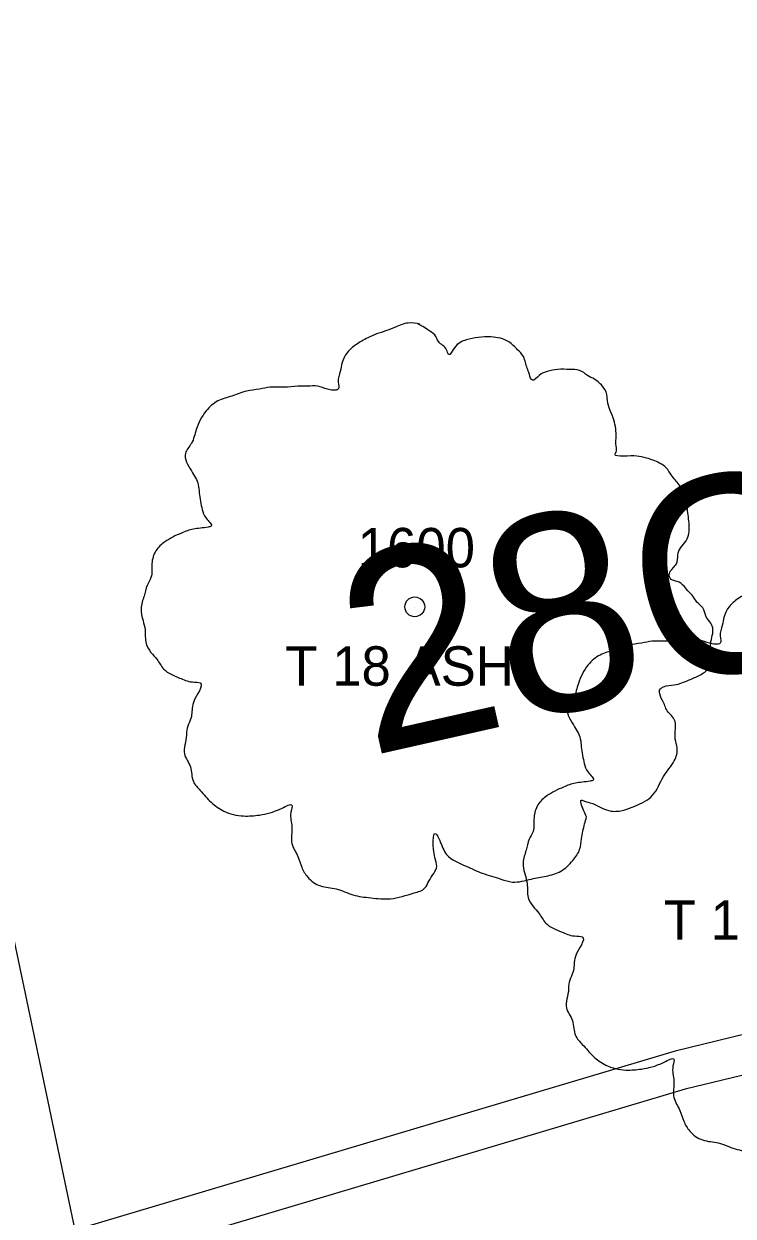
# Model space of a CAD drawing. Extents: x 1964982 to 1970452, y 1116335 to 1119906.
# Drawn here: x 1966603.01 to 1966621, y 1117434.1 to 1117464.33 of the extents above; entities that cross this region are included whole.
import ezdxf

# ---------------------------------------------------------------- set-up
doc = ezdxf.new("R2010")
doc.units = 0
for name, color, linetype in [('RD_EX_VEG', 7, 'Continuous'), ('RD_EX_VEG_txCode', 7, 'Continuous'), ('RD_HC_CL_Rel', 7, 'Continuous'), ('RD_HC_Data_Rel', 7, 'Continuous'), ('RD_PD_CstnLmt', 7, 'Continuous'), ('RD_PD_Final_TrvlWay', 7, 'Continuous'), ('RD_PD_RW', 7, 'Continuous'), ('RD_PD_TX_CstnLmt', 7, 'Continuous')]:
    doc.layers.add(name, color=color, linetype=linetype)

msp = doc.modelspace()

# ---------------------------------------------------------------- linework, layer by layer
at = {"layer": 'RD_EX_VEG'}
for centre, radius in [((1966612.923, 1117449.547), 0.25), ((1966612.923, 1117449.547), 0.25), ((1966612.91, 1117449.528), 0.0001), ((1966612.91, 1117449.528), 0.0001)]:
    msp.add_circle(centre, radius, dxfattribs=at)
for points in [[(1966613.054, 1117456.715), (1966612.755, 1117456.74), (1966612.43, 1117456.64), (1966612.18, 1117456.54), (1966611.955, 1117456.465), (1966611.73, 1117456.365), (1966611.43, 1117456.19), (1966611.205, 1117455.99), (1966611.08, 1117455.74), (1966611.03, 1117455.515), (1966610.98, 1117455.24), (1966610.98, 1117455.065), (1966610.855, 1117455.04), (1966610.705, 1117455.065), (1966610.456, 1117455.14), (1966610.206, 1117455.14), (1966609.956, 1117455.14), (1966609.606, 1117455.115), (1966609.256, 1117455.115), (1966608.981, 1117455.065), (1966608.656, 1117455.015), (1966608.282, 1117454.89), (1966607.932, 1117454.765), (1966607.632, 1117454.515), (1966607.382, 1117454.041), (1966607.257, 1117453.691), (1966607.107, 1117453.441), (1966607.257, 1117452.991), (1966607.432, 1117452.641), (1966607.457, 1117452.441), (1966607.532, 1117452.017), (1966607.632, 1117451.792), (1966607.757, 1117451.592), (1966607.682, 1117451.567), (1966607.307, 1117451.517), (1966607.007, 1117451.417), (1966606.582, 1117451.192), (1966606.357, 1117450.967), (1966606.257, 1117450.642), (1966606.232, 1117450.292), (1966606.133, 1117450.092), (1966606.058, 1117449.818), (1966606.033, 1117449.743), (1966605.983, 1117449.418), (1966606.083, 1117448.968), (1966606.108, 1117448.618), (1966606.232, 1117448.393), (1966606.382, 1117448.218), (1966606.557, 1117447.968), (1966606.957, 1117447.743), (1966607.282, 1117447.643), (1966607.482, 1117447.619), (1966607.307, 1117447.119), (1966607.257, 1117446.769), (1966607.132, 1117446.369), (1966607.132, 1117446.294), (1966607.082, 1117445.819), (1966607.232, 1117445.494), (1966607.307, 1117445.12), (1966607.482, 1117444.895), (1966607.757, 1117444.595), (1966608.082, 1117444.37), (1966608.581, 1117444.245), (1966608.981, 1117444.27), (1966609.556, 1117444.445), (1966609.806, 1117444.52), (1966609.781, 1117444.345), (1966609.806, 1117443.97), (1966609.806, 1117443.545), (1966609.956, 1117443.22), (1966610.056, 1117442.946), (1966610.206, 1117442.696), (1966610.531, 1117442.471), (1966610.93, 1117442.396), (1966611.355, 1117442.246), (1966611.805, 1117442.171), (1966612.305, 1117442.146), (1966612.905, 1117442.296), (1966613.179, 1117442.421), (1966613.279, 1117442.596), (1966613.479, 1117442.971), (1966613.429, 1117443.195), (1966613.454, 1117443.795), (1966613.554, 1117443.62), (1966613.729, 1117443.27), (1966614.229, 1117442.971), (1966614.629, 1117442.796), (1966615.104, 1117442.646), (1966615.403, 1117442.571), (1966615.878, 1117442.646), (1966616.253, 1117442.721), (1966616.628, 1117442.846), (1966616.928, 1117443.12), (1966617.103, 1117443.395), (1966617.153, 1117443.67), (1966617.228, 1117444.045), (1966617.278, 1117444.22)], [(1966613.054, 1117456.715), (1966612.755, 1117456.74), (1966612.43, 1117456.64), (1966612.18, 1117456.54), (1966611.955, 1117456.465), (1966611.73, 1117456.365), (1966611.43, 1117456.19), (1966611.205, 1117455.99), (1966611.08, 1117455.74), (1966611.03, 1117455.515), (1966610.98, 1117455.24), (1966610.98, 1117455.065), (1966610.855, 1117455.04), (1966610.705, 1117455.065), (1966610.456, 1117455.14), (1966610.206, 1117455.14), (1966609.956, 1117455.14), (1966609.606, 1117455.115), (1966609.256, 1117455.115), (1966608.981, 1117455.065), (1966608.656, 1117455.015), (1966608.282, 1117454.89), (1966607.932, 1117454.765), (1966607.632, 1117454.515), (1966607.382, 1117454.041), (1966607.257, 1117453.691), (1966607.107, 1117453.441), (1966607.257, 1117452.991), (1966607.432, 1117452.641), (1966607.457, 1117452.441), (1966607.532, 1117452.017), (1966607.632, 1117451.792), (1966607.757, 1117451.592), (1966607.682, 1117451.567), (1966607.307, 1117451.517), (1966607.007, 1117451.417), (1966606.582, 1117451.192), (1966606.357, 1117450.967), (1966606.257, 1117450.642), (1966606.232, 1117450.292), (1966606.133, 1117450.092), (1966606.058, 1117449.818), (1966606.033, 1117449.743), (1966605.983, 1117449.418), (1966606.083, 1117448.968), (1966606.108, 1117448.618), (1966606.232, 1117448.393), (1966606.382, 1117448.218), (1966606.557, 1117447.968), (1966606.957, 1117447.743), (1966607.282, 1117447.643), (1966607.482, 1117447.619), (1966607.307, 1117447.119), (1966607.257, 1117446.769), (1966607.132, 1117446.369), (1966607.132, 1117446.294), (1966607.082, 1117445.819), (1966607.232, 1117445.494), (1966607.307, 1117445.12), (1966607.482, 1117444.895), (1966607.757, 1117444.595), (1966608.082, 1117444.37), (1966608.581, 1117444.245), (1966608.981, 1117444.27), (1966609.556, 1117444.445), (1966609.806, 1117444.52), (1966609.781, 1117444.345), (1966609.806, 1117443.97), (1966609.806, 1117443.545), (1966609.956, 1117443.22), (1966610.056, 1117442.946), (1966610.206, 1117442.696), (1966610.531, 1117442.471), (1966610.93, 1117442.396), (1966611.355, 1117442.246), (1966611.805, 1117442.171), (1966612.305, 1117442.146), (1966612.905, 1117442.296), (1966613.179, 1117442.421), (1966613.279, 1117442.596), (1966613.479, 1117442.971), (1966613.429, 1117443.195), (1966613.454, 1117443.795), (1966613.554, 1117443.62), (1966613.729, 1117443.27), (1966614.229, 1117442.971), (1966614.629, 1117442.796), (1966615.104, 1117442.646), (1966615.403, 1117442.571), (1966615.878, 1117442.646), (1966616.253, 1117442.721), (1966616.628, 1117442.846), (1966616.928, 1117443.12), (1966617.103, 1117443.395), (1966617.153, 1117443.67), (1966617.228, 1117444.045), (1966617.278, 1117444.22)], [(1966617.278, 1117444.22), (1966617.203, 1117444.395), (1966617.153, 1117444.645), (1966617.228, 1117444.62), (1966617.403, 1117444.57), (1966617.677, 1117444.445), (1966617.902, 1117444.37), (1966618.227, 1117444.395), (1966618.502, 1117444.495), (1966618.952, 1117444.77), (1966619.227, 1117445.245), (1966619.502, 1117445.644), (1966619.577, 1117445.969), (1966619.527, 1117446.194), (1966619.502, 1117446.694), (1966619.302, 1117446.944), (1966619.252, 1117447.069), (1966619.152, 1117447.469), (1966619.227, 1117447.519), (1966619.502, 1117447.569), (1966619.876, 1117447.693), (1966620.151, 1117447.818), (1966620.376, 1117447.993), (1966620.451, 1117448.218), (1966620.426, 1117448.618), (1966620.476, 1117449.018), (1966620.401, 1117449.168), (1966620.301, 1117449.318), (1966620.226, 1117449.518), (1966620.076, 1117449.668), (1966619.976, 1117449.818), (1966619.876, 1117449.917), (1966619.752, 1117450.067), (1966619.577, 1117450.192), (1966619.427, 1117450.242), (1966619.377, 1117450.392), (1966619.527, 1117450.592), (1966619.577, 1117450.692), (1966619.602, 1117450.917), (1966619.827, 1117451.267), (1966619.876, 1117451.667), (1966619.827, 1117452.092), (1966619.777, 1117452.366), (1966619.627, 1117452.641), (1966619.427, 1117452.891), (1966619.302, 1117453.066), (1966619.127, 1117453.191), (1966618.802, 1117453.316), (1966618.552, 1117453.366), (1966618.202, 1117453.366), (1966618.002, 1117453.416), (1966618.027, 1117453.466), (1966618.027, 1117453.616), (1966618.027, 1117453.891), (1966617.952, 1117454.341), (1966617.802, 1117454.84), (1966617.802, 1117454.865), (1966617.702, 1117455.115), (1966617.478, 1117455.315), (1966617.303, 1117455.415), (1966617.103, 1117455.54), (1966616.853, 1117455.565), (1966616.553, 1117455.565), (1966616.278, 1117455.515), (1966616.078, 1117455.415), (1966615.903, 1117455.29), (1966615.828, 1117455.44), (1966615.728, 1117455.74), (1966615.678, 1117455.89), (1966615.528, 1117456.065), (1966615.304, 1117456.265), (1966614.854, 1117456.39), (1966614.229, 1117456.315), (1966613.929, 1117456.115), (1966613.779, 1117455.94), (1966613.729, 1117456.065), (1966613.529, 1117456.265), (1966613.429, 1117456.44), (1966613.254, 1117456.565), (1966613.104, 1117456.665), (1966613.004, 1117456.715)], [(1966617.278, 1117444.22), (1966617.203, 1117444.395), (1966617.153, 1117444.645), (1966617.228, 1117444.62), (1966617.403, 1117444.57), (1966617.677, 1117444.445), (1966617.902, 1117444.37), (1966618.227, 1117444.395), (1966618.502, 1117444.495), (1966618.952, 1117444.77), (1966619.227, 1117445.245), (1966619.502, 1117445.644), (1966619.577, 1117445.969), (1966619.527, 1117446.194), (1966619.502, 1117446.694), (1966619.302, 1117446.944), (1966619.252, 1117447.069), (1966619.152, 1117447.469), (1966619.227, 1117447.519), (1966619.502, 1117447.569), (1966619.876, 1117447.693), (1966620.151, 1117447.818), (1966620.376, 1117447.993), (1966620.451, 1117448.218), (1966620.426, 1117448.618), (1966620.476, 1117449.018), (1966620.401, 1117449.168), (1966620.301, 1117449.318), (1966620.226, 1117449.518), (1966620.076, 1117449.668), (1966619.976, 1117449.818), (1966619.876, 1117449.917), (1966619.752, 1117450.067), (1966619.577, 1117450.192), (1966619.427, 1117450.242), (1966619.377, 1117450.392), (1966619.527, 1117450.592), (1966619.577, 1117450.692), (1966619.602, 1117450.917), (1966619.827, 1117451.267), (1966619.876, 1117451.667), (1966619.827, 1117452.092), (1966619.777, 1117452.366), (1966619.627, 1117452.641), (1966619.427, 1117452.891), (1966619.302, 1117453.066), (1966619.127, 1117453.191), (1966618.802, 1117453.316), (1966618.552, 1117453.366), (1966618.202, 1117453.366), (1966618.002, 1117453.416), (1966618.027, 1117453.466), (1966618.027, 1117453.616), (1966618.027, 1117453.891), (1966617.952, 1117454.341), (1966617.802, 1117454.84), (1966617.802, 1117454.865), (1966617.702, 1117455.115), (1966617.478, 1117455.315), (1966617.303, 1117455.415), (1966617.103, 1117455.54), (1966616.853, 1117455.565), (1966616.553, 1117455.565), (1966616.278, 1117455.515), (1966616.078, 1117455.415), (1966615.903, 1117455.29), (1966615.828, 1117455.44), (1966615.728, 1117455.74), (1966615.678, 1117455.89), (1966615.528, 1117456.065), (1966615.304, 1117456.265), (1966614.854, 1117456.39), (1966614.229, 1117456.315), (1966613.929, 1117456.115), (1966613.779, 1117455.94), (1966613.729, 1117456.065), (1966613.529, 1117456.265), (1966613.429, 1117456.44), (1966613.254, 1117456.565), (1966613.104, 1117456.665), (1966613.004, 1117456.715)], [(1966622.743, 1117450.276), (1966622.443, 1117450.301), (1966622.118, 1117450.201), (1966621.868, 1117450.101), (1966621.643, 1117450.026), (1966621.418, 1117449.926), (1966621.118, 1117449.751), (1966620.893, 1117449.551), (1966620.768, 1117449.301), (1966620.718, 1117449.076), (1966620.669, 1117448.801), (1966620.669, 1117448.626), (1966620.544, 1117448.601), (1966620.394, 1117448.626), (1966620.144, 1117448.701), (1966619.894, 1117448.701), (1966619.644, 1117448.701), (1966619.294, 1117448.676), (1966618.944, 1117448.676), (1966618.669, 1117448.626), (1966618.345, 1117448.576), (1966617.97, 1117448.451), (1966617.62, 1117448.326), (1966617.32, 1117448.077), (1966617.07, 1117447.602), (1966616.945, 1117447.252), (1966616.795, 1117447.002), (1966616.945, 1117446.552), (1966617.12, 1117446.202), (1966617.145, 1117446.002), (1966617.22, 1117445.578), (1966617.32, 1117445.353), (1966617.445, 1117445.153), (1966617.37, 1117445.128), (1966616.995, 1117445.078), (1966616.695, 1117444.978), (1966616.27, 1117444.753), (1966616.046, 1117444.528), (1966615.946, 1117444.203), (1966615.921, 1117443.853), (1966615.821, 1117443.654), (1966615.746, 1117443.379), (1966615.721, 1117443.304), (1966615.671, 1117442.979), (1966615.771, 1117442.529), (1966615.796, 1117442.179), (1966615.921, 1117441.954), (1966616.071, 1117441.779), (1966616.245, 1117441.529), (1966616.645, 1117441.305), (1966616.97, 1117441.205), (1966617.17, 1117441.18), (1966616.995, 1117440.68), (1966616.945, 1117440.33), (1966616.82, 1117439.93), (1966616.82, 1117439.855), (1966616.77, 1117439.38), (1966616.92, 1117439.055), (1966616.995, 1117438.681), (1966617.17, 1117438.456), (1966617.445, 1117438.156), (1966617.77, 1117437.931), (1966618.27, 1117437.806), (1966618.669, 1117437.831), (1966619.244, 1117438.006), (1966619.494, 1117438.081), (1966619.469, 1117437.906), (1966619.494, 1117437.531), (1966619.494, 1117437.106), (1966619.644, 1117436.782), (1966619.744, 1117436.507), (1966619.894, 1117436.257), (1966620.219, 1117436.032), (1966620.619, 1117435.957), (1966621.043, 1117435.807), (1966621.493, 1117435.732), (1966621.993, 1117435.707), (1966622.593, 1117435.857), (1966622.868, 1117435.982), (1966622.968, 1117436.157), (1966623.167, 1117436.532), (1966623.117, 1117436.757), (1966623.142, 1117437.356), (1966623.242, 1117437.181), (1966623.417, 1117436.831), (1966623.917, 1117436.532), (1966624.317, 1117436.357), (1966624.792, 1117436.207), (1966625.092, 1117436.132), (1966625.566, 1117436.207), (1966625.941, 1117436.282), (1966626.316, 1117436.407), (1966626.616, 1117436.682), (1966626.791, 1117436.956), (1966626.841, 1117437.231), (1966626.916, 1117437.606), (1966626.966, 1117437.781)], [(1966622.743, 1117450.276), (1966622.443, 1117450.301), (1966622.118, 1117450.201), (1966621.868, 1117450.101), (1966621.643, 1117450.026), (1966621.418, 1117449.926), (1966621.118, 1117449.751), (1966620.893, 1117449.551), (1966620.768, 1117449.301), (1966620.718, 1117449.076), (1966620.669, 1117448.801), (1966620.669, 1117448.626), (1966620.544, 1117448.601), (1966620.394, 1117448.626), (1966620.144, 1117448.701), (1966619.894, 1117448.701), (1966619.644, 1117448.701), (1966619.294, 1117448.676), (1966618.944, 1117448.676), (1966618.669, 1117448.626), (1966618.345, 1117448.576), (1966617.97, 1117448.451), (1966617.62, 1117448.326), (1966617.32, 1117448.077), (1966617.07, 1117447.602), (1966616.945, 1117447.252), (1966616.795, 1117447.002), (1966616.945, 1117446.552), (1966617.12, 1117446.202), (1966617.145, 1117446.002), (1966617.22, 1117445.578), (1966617.32, 1117445.353), (1966617.445, 1117445.153), (1966617.37, 1117445.128), (1966616.995, 1117445.078), (1966616.695, 1117444.978), (1966616.27, 1117444.753), (1966616.046, 1117444.528), (1966615.946, 1117444.203), (1966615.921, 1117443.853), (1966615.821, 1117443.654), (1966615.746, 1117443.379), (1966615.721, 1117443.304), (1966615.671, 1117442.979), (1966615.771, 1117442.529), (1966615.796, 1117442.179), (1966615.921, 1117441.954), (1966616.071, 1117441.779), (1966616.245, 1117441.529), (1966616.645, 1117441.305), (1966616.97, 1117441.205), (1966617.17, 1117441.18), (1966616.995, 1117440.68), (1966616.945, 1117440.33), (1966616.82, 1117439.93), (1966616.82, 1117439.855), (1966616.77, 1117439.38), (1966616.92, 1117439.055), (1966616.995, 1117438.681), (1966617.17, 1117438.456), (1966617.445, 1117438.156), (1966617.77, 1117437.931), (1966618.27, 1117437.806), (1966618.669, 1117437.831), (1966619.244, 1117438.006), (1966619.494, 1117438.081), (1966619.469, 1117437.906), (1966619.494, 1117437.531), (1966619.494, 1117437.106), (1966619.644, 1117436.782), (1966619.744, 1117436.507), (1966619.894, 1117436.257), (1966620.219, 1117436.032), (1966620.619, 1117435.957), (1966621.043, 1117435.807), (1966621.493, 1117435.732), (1966621.993, 1117435.707), (1966622.593, 1117435.857), (1966622.868, 1117435.982), (1966622.968, 1117436.157), (1966623.167, 1117436.532), (1966623.117, 1117436.757), (1966623.142, 1117437.356), (1966623.242, 1117437.181), (1966623.417, 1117436.831), (1966623.917, 1117436.532), (1966624.317, 1117436.357), (1966624.792, 1117436.207), (1966625.092, 1117436.132), (1966625.566, 1117436.207), (1966625.941, 1117436.282), (1966626.316, 1117436.407), (1966626.616, 1117436.682), (1966626.791, 1117436.956), (1966626.841, 1117437.231), (1966626.916, 1117437.606), (1966626.966, 1117437.781)]]:
    msp.add_spline(points, degree=3, dxfattribs=at)
at = {"layer": 'RD_HC_CL_Rel'}
msp.add_arc((1966373.74, 1118527.456), 1145.915, 281.904723, 295.046328, dxfattribs=at)
at = {"layer": 'RD_HC_Data_Rel'}
msp.add_line((1966610.125, 1117406.187), (1966579.812, 1117549.972), dxfattribs=at)
at = {"layer": 'RD_PD_CstnLmt'}
for p, q in [((1966667.156, 1117448.875), (1966619.782, 1117437.316)), ((1966619.782, 1117437.316), (1966572.088, 1117423.122))]:
    msp.add_line(p, q, dxfattribs=at)
at = {"layer": 'RD_PD_Final_TrvlWay'}
for radius in [1134.915, 1156.915]:
    msp.add_arc((1966373.74, 1118527.456), radius, 281.904723, 295.046328, dxfattribs=at)
at = {"layer": 'RD_PD_RW'}
for p, q in [((1966666.917, 1117449.846), (1966619.521, 1117438.281)), ((1966619.521, 1117438.281), (1966571.829, 1117424.088))]:
    msp.add_line(p, q, dxfattribs=at)

# ---------------------------------------------------------------- texts
at = {"layer": 'RD_EX_VEG_txCode'}
for s, p in [('1600', (1966611.474, 1117450.547)), ('1600', (1966611.474, 1117450.547)), ('T 18 ASH', (1966609.639, 1117447.547)), ('T 18 ASH', (1966609.639, 1117447.547)), ('T 10 OAK', (1966619.233, 1117441.108)), ('T 10 OAK', (1966619.233, 1117441.108))]:
    msp.add_text(s, height=1, dxfattribs=at).set_placement(p)
at = {"layer": 'RD_PD_TX_CstnLmt'}
msp.add_text('28C', height=5, rotation=12.7184, dxfattribs=at).set_placement((1966611.758, 1117445.756))

doc.saveas('drawing.dxf')
